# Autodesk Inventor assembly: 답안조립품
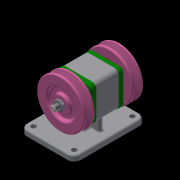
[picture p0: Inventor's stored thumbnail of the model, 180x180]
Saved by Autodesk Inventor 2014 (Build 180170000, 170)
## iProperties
Created: 2020-11
Part Number: 답안조립품
Document SubType Name: Assembly
Designer: kh
Author: kh
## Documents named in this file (10)
- C:\Users\kh\Desktop\701106V1022\답안조립품.iam
- C:\Users\kh\Desktop\701106V1022\본체.ipt
- C:\Users\kh\Desktop\701106V1022\베어링 6004.ipt
- C:\Users\kh\Desktop\701106V1022\축.ipt
- C:\Users\kh\Desktop\701106V1022\커버.ipt
- C:\Users\kh\Desktop\701106V1022\오일 실 17 30 5.ipt
- C:\Users\kh\Desktop\701106V1022\키 5 x 5 x 12.ipt
- C:\Users\kh\Desktop\701106V1022\V-벨트풀리.ipt
- C:\Users\kh\Desktop\701106V1022\너트 M10x1.ipt
- C:\Users\kh\Desktop\701106V1022\볼트 M4.ipt
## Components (2 placed, 1 different names)
1. V-벨트풀리:1
2. V-벨트풀리:2
